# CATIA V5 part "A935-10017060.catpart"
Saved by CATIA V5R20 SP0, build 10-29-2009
Part number: A935-10017060
Source: Unknown
Property "A": "60.000"
Property "ARTICLENO": "A935-10017060"
Property "B": "30.000"
Property "BOMINFO": "A935-10017060"
Property "CODE": "A935-10017060"
Property "L": "170.000"
Property "L1": "127.860"
Property "LINA": "A935-10017060"
Property "NB": "A935-10017060"
Property "NBSYN": "$CODE."
Property "NN": "A935"
Property "NT": "VDI 3357 H-Type Cam Drivers, steel (16MnCr5)"
Property "SUPPLIER": "CF"
Property "T": "60.000"
Property "W": "100.000"
Bounding box of the stored display mesh (mm): x 0 to 170, y 0 to 60, z -100 to 0
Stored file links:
  C:\Users\Utente\Desktop\3D files A935\A935-10017060.catpart
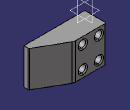
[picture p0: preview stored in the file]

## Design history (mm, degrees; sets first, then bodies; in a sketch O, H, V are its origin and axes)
Body1 "Geometry.1" (main body)
  Solid1 "A935-10017060.catpart": solid without history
